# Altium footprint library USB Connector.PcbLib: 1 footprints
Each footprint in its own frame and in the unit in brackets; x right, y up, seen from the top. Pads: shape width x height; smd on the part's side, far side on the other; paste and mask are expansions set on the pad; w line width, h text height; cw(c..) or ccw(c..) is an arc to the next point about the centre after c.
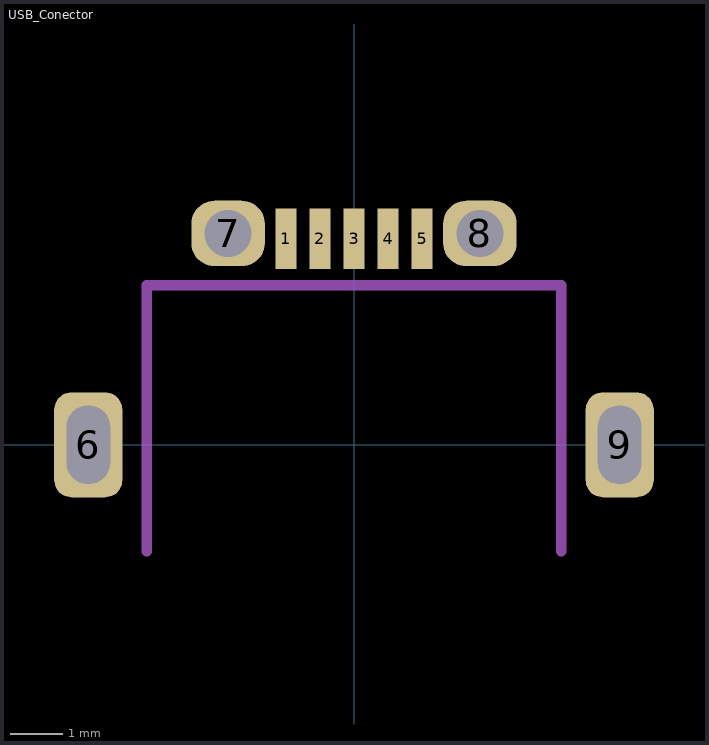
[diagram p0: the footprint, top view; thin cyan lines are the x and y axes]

## USB_Conector [mm]
pads (9):
  rect 0.4x1.15 smd: 1(-1.3,3.925) 2(-0.65,3.925) 3(0,3.925) 4(0.65,3.925) 5(1.3,3.925)
  rrect50% 1.3x2 hole 1.5 slot 0.83 at 0 deg: 6(-5.065,0) 9(5.065,0)
  rrect70% 1.4x1.25 hole 0.9: 7(-2.4,4.03) 8(2.4,4.03)
Mechanical 7:
  lines w0.2: -3.95,-2.03 -3.95,3.04 3.95,3.04 3.95,-2.03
